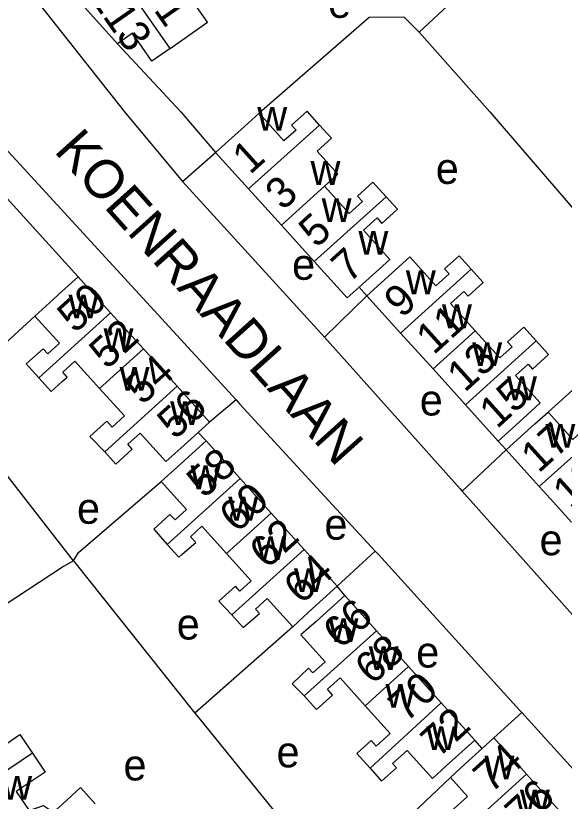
# Model space of a CAD drawing. Extents: x 158356 to 159894, y 383831 to 385260.
# Drawn here: x 158994 to 159064.9, y 384210.9 to 384312.4 of the extents above; entities that cross this region are included whole.
import ezdxf

# ---------------------------------------------------------------- set-up
doc = ezdxf.new("R2010")
doc.units = 0
for name, color, linetype in [('BLT_Basislijn', 7, 'Continuous'), ('BLT_Bebouwing', 7, 'Continuous'), ('BLT_Centroide', 7, 'Continuous'), ('BLT_Huisnummer', 7, 'Continuous'), ('BLT_Huisnummer_ tussenligend', 7, 'Continuous'), ('BLT_Onderverdeling_panden', 7, 'Continuous'), ('BLT_Straatnaam', 7, 'Continuous')]:
    doc.layers.add(name, color=color, linetype=linetype)

msp = doc.modelspace()

# ---------------------------------------------------------------- linework, layer by layer
at = {"layer": 'BLT_Basislijn'}
for p, q in [((159046.11, 384310.29), (159059.22, 384322.41)), ((159022.47, 384262.77), (158982.28, 384306.54)), ((158988.24, 384293.86), (159002.07, 384278.66)), ((159015.56, 384291), (159019.83, 384294.74)), ((159015.56, 384291), (159033.9, 384270.86)), ((159039.38, 384276.22), (159038.38, 384277.34)), ((159033.9, 384270.86), (159039.38, 384276.22)), ((158984.98, 384263.05), (158996.47, 384273.59)), ((159077.31, 384274.39), (159062.8, 384261.18)), ((159001.46, 384241.95), (158984.98, 384263.05)), ((159022.47, 384262.77), (159019.04, 384259.89)), ((159018.59, 384257.46), (159017.55, 384258.55)), ((159056.34, 384257.44), (159057.38, 384256.3)), ((159051.7, 384250.96), (159057.38, 384256.3)), ((159035.55, 384238.68), (159040.45, 384243.21)), ((159001.46, 384241.95), (159017.16, 384222.26)), ((159036.51, 384237.47), (159035.55, 384238.68)), ((159029.8, 384233.44), (159017.16, 384222.26)), ((159055.8, 384219.07), (159059.38, 384222.36)), ((159059.38, 384222.36), (159076.26, 384203.68)), ((159054.29, 384217.71), (159053.32, 384218.8)), ((159050.16, 384213.98), (159035.82, 384200.38))]:
    msp.add_line(p, q, dxfattribs=at)
for points in [[(158995.68, 384315.66), (159008.07, 384300), (159015.56, 384291)], [(159046.11, 384310.29), (159044.21, 384312.2), (159039.67, 384312.17), (159025.45, 384299.81)], [(159046.11, 384310.29), (159055.27, 384300), (159066.72, 384286.68)], [(159007.13, 384308.78), (159015.35, 384300), (159019.83, 384294.74)], [(159033.9, 384270.86), (159051.42, 384251.28), (159051.7, 384250.96)], [(159022.47, 384262.77), (159022.91, 384262.26), (159040.45, 384243.21)], [(159001.46, 384241.95), (159002.1, 384243.05), (159012.79, 384252.22)], [(159069.33, 384231.23), (159069.23, 384231.34), (159051.7, 384250.96)], [(159059.38, 384222.36), (159059.1, 384222.67), (159040.9, 384242.72), (159040.45, 384243.21)], [(159001.46, 384241.95), (159000.15, 384241.24), (158983.15, 384230.05)], [(159017.16, 384222.26), (159017.6, 384221.7), (159027.31, 384209.73), (159035.61, 384200.61), (159035.82, 384200.38)]]:
    msp.add_lwpolyline(points, dxfattribs=at)
at = {"layer": 'BLT_Bebouwing'}
for p, q in [((159007.13, 384308.78), (159001.64, 384314.9)), ((159018.78, 384311.57), (159016.35, 384315.03)), ((159019.83, 384294.74), (159024.08, 384290.03)), ((159024.08, 384290.03), (159028.33, 384285.33)), ((159028.33, 384285.33), (159032.58, 384280.63)), ((159002.07, 384278.66), (159006.26, 384274.02)), ((159039.38, 384276.22), (159043.73, 384271.4)), ((159006.26, 384274.02), (159010.5, 384269.34)), ((159043.73, 384271.4), (159047.92, 384266.76)), ((159010.5, 384269.34), (159014.86, 384264.52)), ((159047.92, 384266.76), (159052.11, 384262.12)), ((159014.86, 384264.52), (159019.04, 384259.89)), ((159052.11, 384262.12), (159056.34, 384257.44)), ((159019.04, 384259.89), (159017.55, 384258.55)), ((159023.01, 384252.58), (159018.59, 384257.46)), ((159061.66, 384251.56), (159057.38, 384256.3)), ((159012.79, 384252.22), (159014.8, 384249.99)), ((159025.33, 384250.01), (159023.01, 384252.58)), ((159063.07, 384250.01), (159061.66, 384251.56)), ((159025.33, 384250.01), (159027.02, 384248.13)), ((159063.07, 384250.01), (159065.82, 384246.96)), ((159027.02, 384248.13), (159031.26, 384243.43)), ((159031.26, 384243.43), (159035.55, 384238.68)), ((159040.6, 384232.92), (159036.51, 384237.47)), ((159044.77, 384228.3), (159040.6, 384232.92)), ((159048.98, 384223.61), (159044.77, 384228.3)), ((159053.32, 384218.8), (159048.98, 384223.61)), ((159054.29, 384217.71), (159055.8, 384219.07)), ((159055.8, 384219.07), (159060.01, 384214.4)), ((159060.01, 384214.4), (159064.28, 384209.67))]:
    msp.add_line(p, q, dxfattribs=at)
for points in [[(159013.96, 384308.19), (159018.78, 384311.57)], [(159013.96, 384308.19), (159011.6, 384306.54), (159009.08, 384310.14), (159007.13, 384308.78)], [(159033.27, 384298.26), (159031.66, 384300.05), (159029.65, 384298.26), (159030.23, 384297.63), (159028.65, 384296.24), (159025.45, 384299.81)], [(159025.45, 384299.81), (159023.54, 384298.09), (159019.83, 384294.74)], [(159033.89, 384290.36), (159035.64, 384291.95), (159032.95, 384294.91), (159034.78, 384296.6), (159033.27, 384298.26)], [(159041.86, 384289.02), (159040.16, 384290.9), (159038.17, 384289.1), (159038.8, 384288.41), (159037.07, 384286.84), (159033.89, 384290.36)], [(159038.38, 384277.34), (159040.53, 384279.28), (159042.35, 384280.92), (159038.94, 384284.69), (159040.69, 384286.28), (159041.3, 384285.57), (159043.32, 384287.41), (159041.86, 384289.02)], [(159032.58, 384280.63), (159036.82, 384275.93), (159038.38, 384277.34)], [(159052.86, 384279.66), (159051.3, 384281.38), (159049.42, 384279.68), (159050, 384279.05), (159048.29, 384277.5), (159044.92, 384281.23), (159043.09, 384279.57), (159039.38, 384276.22)], [(159053.38, 384271.69), (159050.2, 384275.21), (159051.91, 384276.75), (159052.45, 384276.15), (159054.42, 384277.93), (159052.86, 384279.66)], [(158996.47, 384273.59), (158998.36, 384275.31), (159000, 384276.79), (159002.07, 384278.66)], [(158996.47, 384273.59), (158999.65, 384270.07), (158998.14, 384268.7), (158997.53, 384269.37), (158995.35, 384267.4), (158996.96, 384265.61)], [(159061.25, 384270.38), (159059.66, 384272.14), (159057.56, 384270.24), (159058.13, 384269.6), (159056.55, 384268.18), (159053.38, 384271.69)], [(159056.34, 384257.44), (159060.06, 384260.79), (159061.77, 384262.36), (159058.56, 384265.9), (159060.2, 384267.37), (159060.76, 384266.74), (159062.84, 384268.62), (159061.25, 384270.38)], [(158996.96, 384265.61), (158998.58, 384263.83), (159000, 384265.12), (159000.65, 384265.7), (159000.07, 384266.35), (159001.63, 384267.77), (159004.84, 384264.22)], [(159004.84, 384264.22), (159008.04, 384260.68), (159006.44, 384259.23), (159005.76, 384259.99), (159003.58, 384258.02), (159005.5, 384256.05)], [(159070.8, 384259.82), (159069.19, 384261.6), (159067.07, 384259.69), (159067.6, 384259.1), (159065.99, 384257.65), (159062.8, 384261.18)], [(159057.38, 384256.3), (159061.09, 384259.66), (159062.8, 384261.18)], [(159005.5, 384256.05), (159006.92, 384254.47), (159009.04, 384256.39), (159008.48, 384257.02), (159010.08, 384258.47), (159013.4, 384254.79), (159015.33, 384256.54), (159017.55, 384258.55)], [(159018.59, 384257.46), (159014.88, 384254.11), (159012.79, 384252.22)], [(159014.8, 384249.99), (159016.07, 384248.59), (159014.61, 384247.27), (159013.89, 384247.96), (159011.84, 384246.05), (159013.58, 384244.08)], [(159013.58, 384244.08), (159015.08, 384242.42), (159015.47, 384242.78), (159017.03, 384244.11), (159017.25, 384244.31), (159016.56, 384245.07), (159018.06, 384246.42), (159021.23, 384242.91)], [(159021.23, 384242.91), (159024.4, 384239.39), (159022.94, 384238.06), (159022.38, 384238.68), (159020.23, 384236.75), (159021.92, 384234.98)], [(159035.55, 384238.68), (159031.84, 384235.33), (159029.8, 384233.44)], [(159021.92, 384234.98), (159023.4, 384233.35), (159025.5, 384235.16), (159024.99, 384235.73), (159026.5, 384237.09), (159029.8, 384233.44)], [(159036.51, 384237.47), (159032.8, 384234.12), (159030.83, 384232.39), (159033.97, 384228.91), (159032.4, 384227.5), (159031.85, 384228.11), (159029.73, 384226.07), (159031.29, 384224.52)], [(159031.29, 384224.52), (159032.88, 384222.76), (159034.95, 384224.62), (159034.28, 384225.37), (159035.9, 384226.83), (159039.15, 384223.23)], [(159039.15, 384223.23), (159042.39, 384219.63), (159040.59, 384218.01), (159039.93, 384218.74), (159038.07, 384217.07), (159039.8, 384215.15)], [(158989.69, 384219.02), (158990.97, 384217.12), (158994.54, 384219.51), (158996.17, 384217.09)], [(159039.8, 384215.15), (159041.28, 384213.5), (159043.19, 384215.2), (159042.7, 384215.78), (159044.58, 384217.47), (159047.84, 384213.85), (159049.61, 384215.45), (159053.32, 384218.8)], [(159054.29, 384217.71), (159052.09, 384215.72), (159050.16, 384213.98)], [(158996.17, 384217.09), (158997.79, 384214.66), (158994.06, 384212.16), (158995.72, 384209.68)], [(159050.16, 384213.98), (159052.39, 384211.5), (159050.23, 384209.55), (159050.64, 384209.1), (159049.14, 384207.74), (159050.71, 384206)], [(158995.72, 384209.68), (158997.57, 384210.35), (158998.88, 384209.5), (159000.03, 384210.53), (159002.36, 384212.65), (159004.27, 384210.55)]]:
    msp.add_lwpolyline(points, dxfattribs=at)
at = {"layer": 'BLT_Onderverdeling_panden'}
for p, q in [((159013.96, 384308.19), (159006.75, 384318.48)), ((159024.08, 384290.03), (159033.27, 384298.26)), ((159028.33, 384285.33), (159033.89, 384290.36)), ((159032.58, 384280.63), (159041.86, 384289.02)), ((159052.86, 384279.66), (159043.73, 384271.4)), ((158996.96, 384265.61), (159006.26, 384274.02)), ((159053.38, 384271.69), (159047.92, 384266.76)), ((159061.25, 384270.38), (159052.11, 384262.12)), ((159004.84, 384264.22), (159010.5, 384269.34)), ((159005.5, 384256.05), (159014.86, 384264.52)), ((159070.8, 384259.82), (159061.66, 384251.56)), ((159013.58, 384244.08), (159023.01, 384252.58)), ((159021.23, 384242.91), (159027.02, 384248.13)), ((159021.92, 384234.98), (159031.26, 384243.43)), ((159031.29, 384224.52), (159040.6, 384232.92)), ((159039.15, 384223.23), (159044.77, 384228.3)), ((159039.8, 384215.15), (159048.98, 384223.61)), ((158996.17, 384217.09), (158986.7, 384210.73)), ((159050.71, 384206), (159060.01, 384214.4))]:
    msp.add_line(p, q, dxfattribs=at)

# ---------------------------------------------------------------- texts
at = {"layer": 'BLT_Centroide'}
for s, p in [('e', (159034.37, 384312.13)), ('w', (159025.21, 384297.53)), ('e', (159048.28, 384290.67)), ('w', (159032.09, 384290.55)), ('w', (159033.53, 384285.75)), ('w', (159038.28, 384281.52)), ('e', (159029.71, 384278.28)), ('w', (159044.41, 384276.41)), ('w', (159000.81, 384273.3)), ('w', (159049.08, 384272.02)), ('w', (159005.34, 384268.94)), ('w', (159052.99, 384267.12)), ('w', (159007.42, 384263.95)), ('w', (159057.48, 384262.72)), ('e', (159046.21, 384260.74)), ('w', (159013.95, 384259.5)), ('w', (159062.45, 384256.59)), ('w', (159016.59, 384251.22)), ('w', (159021.47, 384247.16)), ('e', (159001.91, 384246.75)), ('e', (159033.89, 384244.69)), ('w', (159025, 384242.05)), ('e', (159061.69, 384242.68)), ('w', (159029.95, 384237.94)), ('e', (159014.8, 384231.79)), ('w', (159034.42, 384231.47)), ('w', (159039.61, 384227.84)), ('e', (159045.75, 384228.17)), ('w', (159041.78, 384222.97)), ('w', (159047.04, 384217.5)), ('e', (159027.7, 384215.27)), ('e', (159007.92, 384213.58)), ('w', (159054.58, 384213.73)), ('w', (158992.25, 384211.09)), ('w', (159059.15, 384209.31))]:
    msp.add_text(s, height=4, dxfattribs=at).set_placement(p)
at = {"layer": 'BLT_Huisnummer'}
for s, rotation, p in [('113', 305.0042, (159003.44, 384314.77)), ('1', 42.102, (159024.26, 384291.77)), ('7', 42.102, (159037.06, 384277.75)), ('50', 42.1134, (159001.64, 384271.26)), ('9', 42.102, (159043.88, 384273.21)), ('15', 42.102, (159056.18, 384258.93)), ('56', 42.1134, (159014.56, 384257.51)), ('17', 42.102, (159061.56, 384253.18)), ('58', 42.0391, (159018.35, 384249.93)), ('64', 42.0391, (159030.9, 384236.22)), ('66', 42.0391, (159035.98, 384230.45)), ('72', 42.0391, (159048.6, 384216.4)), ('74', 42.051, (159055.4, 384211.81))]:
    msp.add_text(s, height=4, rotation=rotation, dxfattribs=at).set_placement(p)
at = {"layer": 'BLT_Huisnummer_ tussenligend'}
for s, rotation, p in [('111', 305.0042, (159008.34, 384318.02)), ('3', 42.102, (159028.51, 384287.12)), ('5', 42.102, (159032.84, 384282.28)), ('11', 42.102, (159048, 384268.48)), ('52', 42.1134, (159005.76, 384266.58)), ('13', 42.102, (159052.01, 384263.63)), ('54', 42.1134, (159010.34, 384261.97)), ('19', 42.102, (159065.67, 384248.55)), ('60', 42.0391, (159022.56, 384245.46)), ('62', 42.0391, (159026.46, 384240.8)), ('68', 42.0391, (159040.09, 384225.82)), ('70', 42.0391, (159044.43, 384220.97)), ('76', 42.051, (159059.5, 384207.12))]:
    msp.add_text(s, height=4, rotation=rotation, dxfattribs=at).set_placement(p)
at = {"layer": 'BLT_Straatnaam'}
msp.add_text('KOENRAADLAAN', height=5, rotation=311.8995, dxfattribs=at).set_placement((158998.83, 384294.88))

doc.saveas('drawing.dxf')
